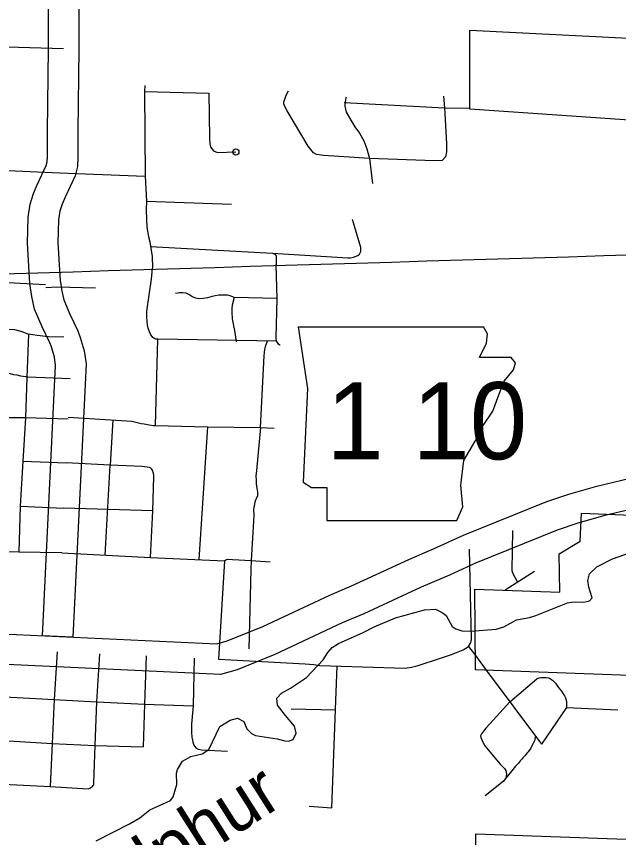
# Model space of a CAD drawing. Extents: x 1212896 to 1368412, y 378476 to 478763.
# Drawn here: x 1302502 to 1307448, y 420570 to 427313 of the extents above; entities that cross this region are included whole.
import ezdxf

# ---------------------------------------------------------------- set-up
doc = ezdxf.new("R2010")
doc.units = 0
for name, color, linetype in [('Level 10', 7, 'Continuous'), ('Level 21', 7, 'Continuous'), ('Level 32', 7, 'Continuous'), ('Level 33', 7, 'Continuous'), ('Level 34', 7, 'Continuous'), ('Level 35', 7, 'Continuous'), ('Level 6', 7, 'Continuous'), ('Level 60', 7, 'Continuous')]:
    doc.layers.add(name, color=color, linetype=linetype)

msp = doc.modelspace()

# ---------------------------------------------------------------- linework, layer by layer
at = {"layer": 'Level 10'}
for points in [[(1302606.9, 425212.1), (1302593.2, 425451.6), (1302598.2, 425664.3), (1302614.8, 425772.3), (1302642.4, 425858.3), (1302673.2, 425931), (1302747.2, 426089), (1302755.1, 426119.7), (1302757.2, 426159.8), (1302756, 426367.9), (1302765, 427049.2), (1302764.9, 428675.3), (1302769.7, 429518), (1302756.1, 430016.4), (1302761.8, 431031.1), (1302765.6, 431144.9), (1302780.6, 431228.2), (1302860.1, 431338.4), (1302922.8, 431388.4), (1302982.9, 431422.2), (1303055, 431450.5), (1303123.2, 431456.9), (1304366.2, 431397.2), (1304803.1, 431383.9)], [(1304792, 431134.1), (1304356.4, 431147.4), (1303128.8, 431206.3), (1303113.5, 431204.9), (1303090.4, 431195.8), (1303062.9, 431180.4), (1303042.8, 431164.3), (1303016.5, 431127.9), (1303014.8, 431118.5), (1303011.7, 431026.2), (1303006.1, 430019.1), (1303019.8, 429520.7), (1303014.9, 428674.6), (1303015, 427047.6), (1303006, 426367), (1303007.3, 426154), (1303003.5, 426081.7), (1302983.5, 426004.1), (1302901.6, 425829.3), (1302877.1, 425771.3), (1302858.9, 425714.7), (1302847.8, 425642.2), (1302843.3, 425455.8), (1302856.2, 425230)], [(1302856.2, 425230), (1302862.2, 425146.5), (1302874.7, 425056.7), (1302890.7, 424986.3), (1302940.4, 424866.9), (1303006.3, 424731.5), (1303026.7, 424677.5), (1303058.4, 424567.5), (1303074.2, 424459.4), (1302966.5, 422215.5)], [(1302716.8, 422227.3), (1302823.3, 424447.3), (1302813.5, 424514.7), (1302789.3, 424598.5), (1302776.5, 424632.3), (1302712.4, 424764.1), (1302651.7, 424910), (1302628.5, 425011.7), (1302613.4, 425120.3), (1302606.9, 425212.1)], [(1301320.2, 422292.8), (1304147.7, 422160.1), (1304233, 422184.8), (1304524.9, 422302.6), (1305075, 422560.6), (1305253.1, 422635.8), (1305725.3, 422854.2), (1305957.8, 422953.9), (1306173.5, 423053), (1306858.2, 423329.3), (1307040.3, 423390.4), (1307270.6, 423456.6), (1307542.5, 423520.2), (1308327.5, 423647.9), (1308845.2, 423714.9), (1310164.8, 423870.3), (1311716.1, 424081.9)], [(1311749.9, 423834.2), (1310196.4, 423622.3), (1308875.9, 423466.8), (1308363.6, 423400.5), (1307591.2, 423274.9), (1307333.7, 423214.6), (1307114.5, 423151.6), (1306944.8, 423094.7), (1306272.5, 422823.4), (1306059.3, 422725.4), (1305827.1, 422625.8), (1305354.2, 422407.1), (1305176.7, 422332.2), (1304624.9, 422073.4), (1304314.8, 421948.2), (1304177.4, 421908.4), (1301308.8, 422043.1)], [(1302966.5, 422215.5), (1302716.8, 422227.3)]]:
    msp.add_lwpolyline(points, dxfattribs=at)
at = {"layer": 'Level 21'}
for p, q in [((1304815.8, 424765), (1304892, 424257.5)), ((1306372.3, 424705.8), (1306337.2, 424764.3)), ((1306363.8, 424629.7), (1306372.3, 424705.8)), ((1306304.6, 424511.3), (1306363.8, 424629.7)), ((1306566.8, 424511.3), (1306304.6, 424511.3)), ((1306600.7, 424469), (1306566.8, 424511.3)), ((1306583.8, 424409.8), (1306600.7, 424469)), ((1306507.6, 424316.7), (1306583.8, 424409.8)), ((1306465.3, 424206.7), (1306507.6, 424316.7)), ((1304892, 424257.5), (1304858.1, 423487.7)), ((1306414.6, 424071.4), (1306465.3, 424206.7)), ((1306330, 423944.5), (1306414.6, 424071.4)), ((1306270.8, 423826.1), (1306330, 423944.5)), ((1306177.7, 423665.4), (1306270.8, 423826.1)), ((1306152.4, 423462.3), (1306177.7, 423665.4)), ((1304858.1, 423487.7), (1304925.8, 423445.4)), ((1304925.8, 423445.4), (1305052.7, 423445.4)), ((1305052.7, 423445.4), (1305052.7, 423174.7)), ((1306169.3, 423284.7), (1306152.4, 423462.3)), ((1306118.5, 423174.7), (1306169.3, 423284.7)), ((1305052.7, 423174.7), (1306118.5, 423174.7))]:
    msp.add_line(p, q, dxfattribs=at)
msp.add_lwpolyline([(1304815.8, 424765), (1306337.2, 424764.3)], dxfattribs=at)
at = {"layer": 'Level 32'}
msp.add_lwpolyline([(1306272.2, 422063.5), (1306361.4, 421944.2)], dxfattribs=at)
at = {"layer": 'Level 33'}
for points in [[(1301557.6, 427075.4), (1302055.4, 427075.1), (1302890, 427048.4)], [(1303556.7, 426744.6), (1303554.2, 426695.2), (1303559.1, 426001.3), (1303569.4, 425794.7), (1303567.5, 425725.5), (1303569.6, 425646.3), (1303572.7, 425581.1), (1303580.7, 425537), (1303586.8, 425501.9), (1303596.8, 425460.8), (1303605.9, 425409.7), (1303616, 425341.5), (1303621.1, 425245.2)], [(1303554.2, 426695.2), (1304083, 426681.9)], [(1304083, 426681.9), (1304087.4, 426315.8), (1304091.5, 426266.7), (1304094.5, 426253.7), (1304099.5, 426236.6), (1304119.9, 426209.9), (1304152.6, 426194.6), (1304304.5, 426199.8)], [(1301574.3, 426084.6), (1302857.4, 426029.5), (1303559.1, 426001.3)], [(1303569.3, 425796.9), (1304268.8, 425769.8)], [(1303643.2, 423954.5), (1303663.9, 424662.2), (1303647.3, 424663.6), (1303638.3, 424666.5), (1303631.5, 424669.7), (1303622, 424677.1), (1303609.7, 424694.4), (1303603.9, 424704), (1303595.4, 424721.5), (1303584.8, 424751.8), (1303579.2, 424776.6), (1303572, 424841.8), (1303573.7, 424892.7), (1303610.9, 425155.6), (1303621.1, 425245.2)], [(1302741.2, 425108.1), (1302432.3, 425125.9), (1302432.7, 425080.8), (1302433, 425056.7), (1302425.3, 425023.6), (1302417.8, 425006.5), (1302412.6, 425000.4), (1302394.7, 424989.4), (1302353.8, 424984.1), (1302303.6, 424997.9), (1302251, 425002.7), (1301601.7, 425013.6)], [(1302892.7, 424678.6), (1302766, 424680.5), (1302739.2, 424683.4), (1302717.8, 424686), (1302696.9, 424689.2), (1302671.8, 424693.3), (1302636.7, 424697.5), (1302599.1, 424703.8), (1302540, 424725.8), (1302488.5, 424738.6), (1302194.4, 424744.6), (1301726.9, 424751.5), (1301609.2, 424752.3), (1298331.2, 424884.3), (1297118.9, 424921.4)], [(1302600.9, 424703.5), (1302587.8, 424349), (1302576.3, 424017.2), (1302556, 423660.2), (1302531.8, 423291.2), (1302521.7, 422914.4)], [(1302943.1, 424336.4), (1302595.8, 424350.1), (1302539.2, 424359), (1302508.9, 424366.2), (1302480, 424370.8), (1302453.9, 424377.6), (1302416.9, 424384.2), (1302373.9, 424393.8), (1302333.9, 424404.4), (1302291.9, 424417.9), (1302269.3, 424427.8), (1302252.9, 424436.4), (1302236.7, 424450.4), (1302213.6, 424466.2), (1302194.5, 424475), (1302158.6, 424478.6), (1301911.5, 424476.8), (1301851.1, 424502.6), (1301807, 424509.1), (1301610.6, 424514.8), (1301518.7, 424525.8), (1301206.8, 424538.4)], [(1302927.2, 424005.2), (1302576.3, 424017.2), (1302440.5, 424015.2), (1302411.8, 424015.8), (1302394.4, 424018.8), (1302381.8, 424023), (1302360.9, 424029.6), (1302335.7, 424039.2), (1302309.4, 424048.8), (1302280.6, 424065.6), (1302253.1, 424080.5), (1302227.3, 424095.6), (1302192.3, 424111.2), (1302167.2, 424123), (1302142.2, 424130.7), (1302112.2, 424134.4), (1301552.5, 424151.5), (1301206.3, 424163.5)], [(1302928.1, 424023), (1303449.3, 423988.5), (1303494.3, 423979.5), (1303525.4, 423971), (1303551.9, 423966.1), (1303591.2, 423958.9), (1303629.2, 423954.4), (1303643.2, 423954.5), (1304070.2, 423943.1), (1304507.1, 423936.8), (1304617.8, 423931.1)], [(1304070.2, 423943.1), (1304000, 422851.9)], [(1304507.1, 423936.8), (1304472.9, 423583.7), (1304468.5, 423538.4), (1304470.5, 423505.6), (1304471.9, 423478.5), (1304475.2, 423453.4), (1304482, 423407.5), (1304482.8, 423396.4), (1304481, 423375.4), (1304471.2, 423351.2), (1304466.6, 423339.2), (1304460.8, 423322.8), (1304454.1, 423294.9), (1304450.2, 423266.8), (1304450.7, 423213.7), (1304430.5, 422844.7), (1304426.3, 422769.5), (1304410.3, 422119.8)], [(1302556, 423660.2), (1302910, 423646.5)], [(1303604.4, 422869.9), (1303621.4, 423252.9), (1303631.5, 423533.5), (1303630.4, 423547.6), (1303629.3, 423553.6), (1303628.3, 423559.6), (1303625.7, 423568.5), (1303621.3, 423580), (1303612.9, 423596.5), (1303609.6, 423600.8), (1303605, 423604.3), (1303599.3, 423607), (1303593.8, 423609.3), (1303534.9, 423615.7), (1303272.5, 423628.9), (1302910, 423646.5)], [(1303232.2, 422889.5), (1303272.5, 423628.9)], [(1302531.8, 423291.2), (1302892.1, 423274.1)], [(1303621.4, 423252.9), (1302892.1, 423274.1)], [(1304162.5, 422034.2), (1304874.4, 421996.9), (1304943.9, 421990.4), (1304993.2, 421984), (1305694.4, 421960.5), (1305747.8, 421968.6), (1305801.9, 421982.7), (1305868.5, 422003.5), (1305918.2, 422020.1), (1306002.3, 422047.8), (1306074.2, 422073.7), (1306171.1, 422112.5), (1306216.4, 422138.3), (1306232.5, 422167.4), (1306240.6, 422193.3), (1306223, 422938.2)], [(1302874.6, 422908.4), (1302521.7, 422914.4), (1302156.5, 422924.5)], [(1302874.6, 422908.4), (1303604.4, 422869.9), (1304210.1, 422842.4), (1304222.1, 422851.6), (1304236.9, 422856.7), (1304277.8, 422854.1), (1304430.5, 422844.7), (1304585.7, 422835.1)], [(1304210.1, 422842.4), (1304161.1, 422034.3)], [(1300999.1, 421077.5), (1301353.8, 421050.1), (1301704, 421038.8), (1302064.3, 421024.7), (1302779.8, 420988.3), (1303090.2, 420970.6), (1303104.1, 420975.2), (1303113.9, 420980.7), (1303120.7, 420985.8), (1303126, 420990), (1303131.8, 420996.1), (1303133.8, 420999.1), (1303136.6, 421004), (1303138.2, 421009.4), (1303138.6, 421018.2), (1303149.4, 421324.9), (1303162.7, 421683.8), (1303188, 422079.3)], [(1302835.6, 422095.6), (1302813.4, 421704.1), (1302796.1, 421343.2), (1302779.8, 420988.3)], [(1303567.5, 422061.7), (1303552.9, 421664.9), (1303542.5, 421316.1)], [(1303963, 422043.5), (1303954, 421650.2), (1303939.6, 421501.8), (1303939.1, 421453.7), (1303940.4, 421422.6), (1303942.6, 421405.6), (1303943.7, 421393.6), (1303947.9, 421370.6), (1303952.1, 421352.6), (1303960.3, 421329.7), (1303976.5, 421306.8), (1303995.5, 421297), (1304021.5, 421291.2), (1304236.1, 421279.5)], [(1301027, 421794), (1301382.3, 421771.8), (1301734.6, 421756.6), (1302095.9, 421737.4), (1302455.1, 421721.3), (1302813.4, 421704.1), (1303162.7, 421683.8), (1303552.9, 421664.9), (1303954, 421650.2)], [(1301012.7, 421426.3), (1301367.1, 421409), (1301721.3, 421402.7), (1302079.6, 421379.6), (1302437.8, 421364.4), (1302796.1, 421343.2), (1303149.4, 421324.9), (1303542.5, 421316.1)]]:
    msp.add_lwpolyline(points, dxfattribs=at)
msp.add_circle((1304304.5, 426199.8), 25, dxfattribs=at)
at = {"layer": 'Level 34'}
for points in [[(1306010.4, 426658.9), (1306017.2, 426563), (1306034.5, 426269.2), (1306035.3, 426202.1), (1306026.6, 426159.7), (1305999.7, 426130.7), (1305935.3, 426126.5), (1305402, 426146), (1305023.8, 426171.9), (1304966.2, 426177.6), (1304942.2, 426192.6), (1304899.1, 426246.7), (1304724.8, 426537.9), (1304702.8, 426577.4), (1304697.8, 426595.4), (1304697.7, 426607.4), (1304716.7, 426665.6), (1304736.3, 426702.9)], [(1305209.7, 426649.8), (1305207.4, 426643.2), (1305201.5, 426612.1), (1305199.5, 426577), (1305211.6, 426527.9), (1305247.7, 426459.7), (1305281.7, 426406.6), (1305318.8, 426354.5), (1305356.8, 426291.4), (1305379.9, 426224.2), (1305402, 426146), (1305409.1, 426077.8), (1305427.3, 425940.5)], [(1305193.5, 426607.1), (1306017.2, 426563), (1306225.1, 426559.6)], [(1303603.6, 425422.5), (1304606.4, 425367.8), (1305224.9, 425330.2), (1305246.2, 425330.5), (1305271.2, 425335.6), (1305305.1, 425348.7), (1305321.1, 425360.7), (1305330.1, 425382.8), (1305332, 425415.9), (1305263.7, 425645.4)], [(1304606.4, 425367.8), (1304629, 425358.7), (1304636.1, 425342.9), (1304635.6, 425271.6)], [(1304668.4, 424611.9), (1304666.8, 424612.8), (1304654.7, 424622.7), (1304645.6, 424634.6), (1304638.5, 424646.6), (1304636.3, 424673.6), (1304644.9, 424995.4), (1304635.6, 425271.6)], [(1302744.3, 425087.9), (1302833.6, 425092.1), (1303152.8, 425083.5)], [(1304644.9, 424995.4), (1304291.7, 425005.6), (1304257.7, 425017.2), (1304236.4, 425022.5), (1304217.7, 425023.8), (1304189.8, 425024.5), (1304164.9, 425024.3), (1304134, 425018.9), (1304109.1, 425012.6), (1304070.3, 425003.2), (1304034.8, 424995.5), (1304001.6, 424994.5), (1303974.6, 424999.2), (1303954.6, 425008), (1303943.1, 425013.1), (1303918.4, 425029.6), (1303895.3, 425039.3), (1303868, 425043.3), (1303840.8, 425041.7), (1303809.6, 425036.5)], [(1304291.7, 425005.6), (1304275.4, 424941.3), (1304271.7, 424918.2), (1304270.3, 424884.9), (1304273.6, 424830), (1304276.7, 424817), (1304281, 424788), (1304285.2, 424771), (1304291.4, 424748.1), (1304296.7, 424718.3), (1304306.1, 424641.3)], [(1304638.5, 424646.6), (1303663.9, 424662.2)], [(1304507.1, 423936.8), (1304537, 424525.3), (1304539.7, 424552.3), (1304542.5, 424576.4), (1304544.4, 424588.5), (1304547.4, 424602.2), (1304564.4, 424647.5)], [(1303294.1, 423998.8), (1303272.5, 423628.9)], [(1306576.6, 423090.6), (1306571.6, 422763.1), (1306578.8, 422737.2), (1306616.1, 422673.1)], [(1306757.5, 422754.6), (1306516.9, 422601.6)], [(1306216.4, 422138.3), (1306272.2, 422063.5)], [(1304907.2, 420828.7), (1305092.7, 420812.8), (1305123.3, 421622.7), (1305136.8, 421979.2)], [(1306361.4, 421944.2), (1306814.9, 421337.3)], [(1306555.8, 421684), (1306776.5, 421874), (1306780.5, 421877), (1306795.4, 421882.2), (1306809.3, 421884.4), (1306826, 421885.3), (1306840.2, 421884.7), (1306854.2, 421883.9), (1306872.4, 421882.1), (1306880.2, 421879.1), (1306905.7, 421863), (1306928.5, 421838.6), (1306952.8, 421804.8), (1306979, 421773), (1306993.4, 421749), (1307003.5, 421732.4), (1307011.6, 421717.9), (1307016.7, 421699.2), (1307019.8, 421684.2), (1307020, 421666.2), (1307019.2, 421645.1), (1307019.3, 421639.1), (1306814.9, 421337.3)], [(1306555.8, 421684), (1306390.9, 421504.8), (1306357.6, 421468.2), (1306337.4, 421443.5), (1306321.6, 421422.9), (1306315.1, 421406.4), (1306316.6, 421392.1), (1306333, 421352.2), (1306348.2, 421323.3), (1306474.5, 421171.3), (1306496.3, 421151.6), (1306510.9, 421137.5), (1306521.4, 421119.7), (1306525, 421105.8), (1306528.2, 421086.5), (1306521, 421057.5), (1306498.9, 421030.3), (1306352.5, 420911.5)], [(1304758.2, 421626.8), (1305123.2, 421619.8)], [(1307019.3, 421639.1), (1307440.4, 421618.6)], [(1306765.2, 421403.8), (1306756.9, 421365.4), (1306746.9, 421343), (1306729.1, 421311.2), (1306726.4, 421305), (1306705.6, 421274.1), (1306694.1, 421262.6), (1306679.9, 421244), (1306662.7, 421224.3), (1306655.1, 421214.9), (1306642.6, 421202.4), (1306625.5, 421181.6), (1306602.5, 421155.6), (1306591.1, 421142.1), (1306570.1, 421118.2), (1306521, 421057.5)]]:
    msp.add_lwpolyline(points, dxfattribs=at)
at = {"layer": 'Level 35'}
for points in [[(1304258.9, 421533.8), (1304317.6, 421549.5), (1304368.8, 421522), (1304394.3, 421462.1), (1304432.6, 421424.5), (1304465.3, 421406.5), (1304644.5, 421381.7), (1304706.5, 421363.3), (1304737.5, 421362.6), (1304774.1, 421375.7), (1304800.7, 421427.5), (1304787.1, 421484.4), (1304711.4, 421570.8), (1304645.3, 421656.1), (1304641.1, 421714.3), (1304678.6, 421754.8), (1304752, 421795.6), (1304884.7, 421883.2), (1305020.9, 422029), (1305060.2, 422088.5), (1305094.7, 422130), (1305147.2, 422162.6), (1305350.8, 422253), (1305439.1, 422299), (1305614.8, 422374.1), (1305852.6, 422438.8), (1305943.3, 422444.4), (1305998.4, 422417.3), (1306032.6, 422394.6), (1306081.4, 422303.9), (1306111.5, 422284.2), (1306161.5, 422266.7), (1306232.4, 422264.5), (1306442.7, 422281.8), (1306505.5, 422299.8), (1306608.5, 422357.7), (1306716, 422376.9), (1306768.7, 422393.5), (1307028.9, 422498.5), (1307076.7, 422506), (1307162.6, 422502), (1307209.9, 422512.5), (1307229.8, 422539.4), (1307204.2, 422625.6), (1307194.7, 422680.7), (1307209.1, 422734.9), (1307268.3, 422791.7), (1307398.3, 422858.2), (1307546.4, 422909.9)], [(1303155.9, 420542), (1303429.8, 420681.2), (1303516, 420732.2), (1303597.2, 420797.2), (1303768, 420874.2), (1303788.6, 420905.5), (1303820.5, 421005), (1303816.5, 421098.2), (1303824.2, 421127.3), (1303865.4, 421197.9), (1303934.8, 421235.7), (1304027.4, 421257.8), (1304081.8, 421293.4), (1304174.1, 421482.1), (1304258.9, 421533.8)]]:
    msp.add_lwpolyline(points, dxfattribs=at)
at = {"layer": 'Level 6'}
for points in [[(1307561.5, 425361.5), (1307537.6, 426460.1), (1306225.1, 426550.2), (1306226, 427201.1)], [(1306226, 427201.1), (1307530, 427135.6)], [(1306268.2, 422610.7), (1306964, 422585.2), (1306961.1, 422900.6), (1307133.6, 423002.9), (1307142, 423232.6), (1307556.4, 423217.4), (1307557.5, 423097.3), (1308020.7, 423174), (1308339.7, 423144.2), (1308341.1, 422990.9)], [(1306273.1, 421947.5), (1306268.2, 422610.7)], [(1308880.3, 421852.2), (1306273.1, 421947.5)], [(1298282, 416932.8), (1298296.1, 418277.7), (1300953.3, 418184), (1300954.1, 417707.1), (1301264.5, 417691.4), (1301267.6, 418169.4), (1302325.3, 418129.7), (1302316.8, 419451.2), (1306281.1, 419306.5), (1306275.8, 420601.1), (1308897.1, 420508), (1308880.3, 421852.2)]]:
    msp.add_lwpolyline(points, dxfattribs=at)
at = {"layer": 'Level 60'}
msp.add_spline([(1257400.5, 423880.1), (1274492.7, 424373.3), (1311685.6, 425480.9), (1319317.4, 425714)], degree=3, dxfattribs=at)

# ---------------------------------------------------------------- texts
at = {"layer": 'Level 21'}
msp.add_text('1 10', height=633.6, dxfattribs=at).set_placement((1305048.1, 423675.6))
at = {"layer": 'Level 35'}
msp.add_text('Sulphur', height=422.4, rotation=32.48524, dxfattribs=at).set_placement((1303067.2, 419800.4))

doc.saveas('drawing.dxf')
